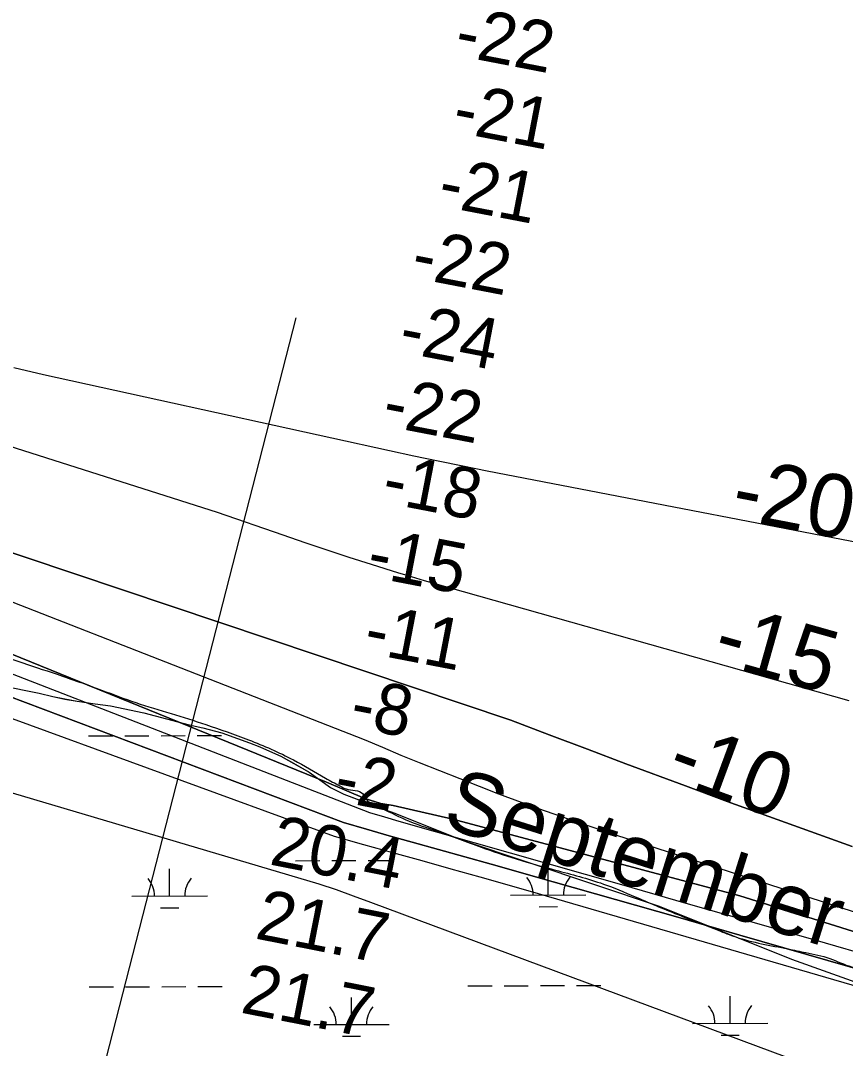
# Model space of a CAD drawing. Extents: x 3361039 to 3398939, y 576572 to 602007.
# Drawn here: x 3394047 to 3395141, y 583372 to 584734 of the extents above; entities that cross this region are included whole.
import ezdxf

# ---------------------------------------------------------------- set-up
doc = ezdxf.new("R2010")
doc.units = 0
for name, color, linetype in [('V-RIVR-EDGE', 7, 'Continuous'), ('V-RIVR-IDEN', 7, 'Continuous'), ('V-RIVR-RANG', 7, 'Continuous'), ('V-SITE-VEGE', 7, 'Continuous'), ('V-TOPO-DPTH', 7, 'Continuous'), ('V-TOPO-MINR', 7, 'Continuous'), ('V-TOPO-MINR-IDEN', 7, 'Continuous'), ('V-TOPO-WATR', 7, 'Continuous'), ('V-WETL-SWMP', 7, 'Continuous')]:
    doc.layers.add(name, color=color, linetype=linetype)

msp = doc.modelspace()

# ---------------------------------------------------------------- linework, layer by layer
at = {"layer": 'V-RIVR-EDGE'}
msp.add_spline([(3387368.6, 585771), (3387389, 585767.6), (3387407.3, 585766.1), (3387418.2, 585761.7), (3387425.5, 585756.5), (3387441.6, 585752.8), (3387452.6, 585751.4), (3387462.1, 585753.9), (3387477.4, 585758.2), (3387482.9, 585759.3), (3387491.7, 585759.3), (3387502.3, 585758.2), (3387510.3, 585756.3), (3387521.6, 585753), (3387530.1, 585752.3), (3387538.5, 585752.2), (3387549.8, 585752.2), (3387558.9, 585755.5), (3387571.4, 585756.9), (3387583.4, 585757.3), (3387598.4, 585756.1), (3387629.8, 585749.5), (3387659.8, 585743.5), (3387703.3, 585736.8), (3387727.4, 585734.2), (3387739.1, 585733.5), (3387750.8, 585734.2), (3387753.7, 585731.6), (3387763.2, 585723.9), (3387774.5, 585720.6), (3387790.6, 585719.8), (3387800.1, 585721.6), (3387814, 585720.1), (3387824.6, 585720.1), (3387847.3, 585714.2), (3387884.2, 585709.4), (3387930.2, 585702.7), (3387980.6, 585701.1), (3388035.1, 585696.5), (3388076, 585694.6), (3388096.9, 585693.8), (3388120.3, 585690.5), (3388145.1, 585685.3), (3388171.8, 585682.3), (3388198.8, 585676.8), (3388222.6, 585669.4), (3388245.6, 585660.6), (3388260.9, 585655.4), (3388279.6, 585655.4), (3388291.3, 585658.3), (3388298.9, 585663.7), (3388299.3, 585666.3), (3388299, 585670.7), (3388290.6, 585674.4), (3388291.7, 585677.3), (3388293.9, 585678.4), (3388303, 585677.6), (3388318.7, 585676.5), (3388334.1, 585672.8), (3388354.1, 585663.6), (3388357.1, 585659.9), (3388363.3, 585658.1), (3388368.4, 585658.1), (3388371, 585661), (3388375.3, 585662.1), (3388379, 585661.3), (3388383, 585659.1), (3388383.7, 585654.4), (3388384.1, 585649.3), (3388389.9, 585647.4), (3388406, 585642.3), (3388468.9, 585637.7), (3388491.5, 585635.8), (3388534.6, 585628.4), (3388578.1, 585619.2), (3388610.6, 585613.6), (3388635.9, 585612.1), (3388727.9, 585599.4), (3388768.5, 585591.7), (3388822.6, 585580.9), (3388865, 585570.6), (3388906.6, 585562.8), (3388924.1, 585559.5), (3388938.8, 585562), (3388961.4, 585563.4), (3388974.2, 585560.1), (3389007.5, 585553.4), (3389018.8, 585554.5), (3389027.2, 585555.9), (3389037.1, 585555.9), (3389051.7, 585553.7), (3389061.2, 585553.3), (3389081.3, 585552.1), (3389098.1, 585551), (3389120.4, 585548.7), (3389143.4, 585546.5), (3389160.2, 585542.1), (3389200.8, 585534.7), (3389222.3, 585525.1), (3389247.2, 585519.2), (3389280.4, 585509.6), (3389307.5, 585497.8), (3389334.5, 585487.2), (3389349.5, 585483.1), (3389361.5, 585483.1), (3389382.7, 585479), (3389397, 585476.8), (3389416.7, 585468.7), (3389441.9, 585458.4), (3389464.9, 585451.4), (3389479.5, 585449.2), (3389506.2, 585446.2), (3389533.2, 585447.2), (3389558.5, 585444.2), (3389577.8, 585437.9), (3389603.4, 585431.3), (3389618.7, 585425.1), (3389639.2, 585415.1), (3389657.8, 585410.3), (3389693.2, 585404.8), (3389768.9, 585383), (3389806.5, 585373), (3389854.3, 585362.3), (3389881.7, 585358.6), (3389913.9, 585354.5), (3389953.7, 585349.3), (3390008.2, 585341.8), (3390037.8, 585336.3), (3390074.3, 585327.8), (3390128, 585312.7), (3390164.5, 585301.6), (3390200.7, 585289.8), (3390292.7, 585255.6), (3390327.1, 585241.3), (3390360.7, 585231.7), (3390404.5, 585221), (3390454.9, 585214.3), (3390483.1, 585210.5), (3390491.8, 585209.4), (3390494.4, 585207.2), (3390501.3, 585201), (3390507.9, 585200.6), (3390527.3, 585196.2), (3390545.9, 585195), (3390557.6, 585194.3), (3390574.4, 585189.8), (3390605.5, 585179.5), (3390698.6, 585148.2), (3390763.2, 585126.9), (3390811.1, 585111), (3390852.4, 585097.8), (3390900.9, 585081.6), (3390948.1, 585063.5), (3390993.7, 585048.4), (3391036.8, 585031.9), (3391070.8, 585020.1), (3391140.5, 584997.6), (3391201.5, 584974.1), (3391247.5, 584957.5), (3391310.7, 584933.6), (3391362.2, 584914.8), (3391400.6, 584900.1), (3391441.8, 584885.7), (3391505.4, 584861.1), (3391563.5, 584841.9), (3391658.8, 584807.3), (3391712.8, 584786), (3391758.8, 584767.3), (3391796.1, 584749.6), (3391880.4, 584718.3), (3391926.8, 584701.4), (3391969.2, 584685.2), (3392003.9, 584666.9), (3392040, 584650.3), (3392077.6, 584636), (3392135.7, 584613.2), (3392164.9, 584598.1), (3392196, 584583.8), (3392224.8, 584578.2), (3392263.5, 584567.9), (3392290.6, 584559.8), (3392322.7, 584546.5), (3392396.5, 584512.7), (3392439.9, 584496.2), (3392471.7, 584484.8), (3392502, 584473.3), (3392510.8, 584467.5), (3392535.2, 584458.3), (3392606.1, 584432.9), (3392632.4, 584421.5), (3392666.7, 584406.8), (3392715.6, 584386.9), (3392777.4, 584364.8), (3392827, 584348.3), (3392863.6, 584335.4), (3392897.9, 584321.8), (3392928.6, 584307.8), (3392965.4, 584294.9), (3393010, 584279.1), (3393054.6, 584263.2), (3393092.5, 584248.5), (3393195.2, 584206.6), (3393234.2, 584187.9), (3393264.5, 584173.5), (3393294.1, 584162.1), (3393336.8, 584147.4), (3393374.5, 584136.3), (3393402.2, 584127.5), (3393414.3, 584119.8), (3393435.4, 584109.1), (3393459.2, 584098.1), (3393478.9, 584087.5), (3393513.6, 584076.4), (3393541.7, 584067.2), (3393588.1, 584047.4), (3393643.2, 584028.9), (3393668.4, 584018.3), (3393699.8, 584005), (3393737.1, 583991.8), (3393781.7, 583976), (3393884.7, 583943.2), (3393927, 583928.8), (3393981.1, 583908.2), (3394043.9, 583885.4), (3394095.8, 583868.1), (3394154.9, 583847.1), (3394200.2, 583830.5), (3394247, 583816.2), (3394293, 583801.4), (3394349.6, 583781.2), (3394409.1, 583754.7), (3394451.8, 583730.5), (3394470.5, 583720.2), (3394481.8, 583715.4), (3394494.2, 583713.6), (3394502.6, 583708.1), (3394507.3, 583700.4), (3394511.3, 583697.8), (3394522.7, 583692.3), (3394557.3, 583675.8), (3394600.4, 583659.9), (3394658.1, 583638.9), (3394704.5, 583623.5), (3394760.4, 583607.6), (3394824, 583588.8), (3394867.8, 583570.8), (3394925.9, 583546.9), (3394972.2, 583528.9), (3394995.6, 583520), (3395064.7, 583504.2), (3395088.4, 583499.3), (3395120.2, 583491.6), (3395149.1, 583480.5), (3395173.2, 583476.8), (3395201.3, 583471.3), (3395236.4, 583459.9), (3395256.8, 583451.8), (3395280.9, 583445.5), (3395300.3, 583445.1), (3395316.7, 583440.7), (3395324.4, 583433.3), (3395335.3, 583426), (3395353.6, 583417.9), (3395398.9, 583403.9), (3395426.3, 583397.2), (3395442, 583391), (3395455.9, 583383.3), (3395476, 583377.8), (3395495.7, 583369.3), (3395511, 583368.2), (3395530.4, 583365.9), (3395550.5, 583361.8), (3395654.6, 583334.9), (3395704.7, 583322.4), (3395743.7, 583306.9), (3395765.3, 583295.5), (3395788.3, 583286.3), (3395816.4, 583278.9), (3395861.7, 583270.8), (3395916.2, 583261.5), (3395960.7, 583252.6), (3396008.6, 583242.6), (3396060.8, 583230.5), (3396093.4, 583222.3), (3396135.4, 583208.7), (3396170.1, 583199.8), (3396204.4, 583191.3), (3396254.8, 583177.3), (3396301.2, 583165.9), (3396364.4, 583152.9), (3396399.1, 583144.4), (3396426.9, 583138.5), (3396463.1, 583133), (3396489.8, 583132.9), (3396523.4, 583130.2), (3396607.8, 583114), (3396670.3, 583102.1), (3396708.3, 583095.4), (3396743, 583089.5), (3396775.1, 583083.9)], degree=3, dxfattribs=at)
at = {"layer": 'V-RIVR-RANG'}
msp.add_line((3394114.5, 583178.3), (3394413, 584340.6), dxfattribs=at)
at = {"layer": 'V-SITE-VEGE'}
for p, q in [((3394037.2, 583850), (3394056.8, 583846.3)), ((3394056.8, 583846.3), (3394072.3, 583842.9)), ((3394072.3, 583842.9), (3394090.2, 583838.7)), ((3394090.2, 583838.7), (3394106, 583835.3)), ((3394106, 583835.3), (3394122.6, 583832.4)), ((3394122.6, 583832.4), (3394146.4, 583829.1)), ((3394146.4, 583829.1), (3394166.6, 583826.2)), ((3394166.6, 583826.2), (3394210.7, 583817)), ((3394210.7, 583817), (3394271.2, 583801.2)), ((3394271.2, 583801.2), (3394289.2, 583797.1)), ((3394289.2, 583797.1), (3394314.4, 583790.6)), ((3394314.4, 583790.6), (3394335.2, 583783.2)), ((3394335.2, 583783.2), (3394350.9, 583777.4)), ((3394350.9, 583777.4), (3394364.6, 583772.1)), ((3394364.6, 583772.1), (3394381.5, 583764.6)), ((3394381.5, 583764.6), (3394392.5, 583759.5)), ((3394392.5, 583759.5), (3394430, 583738.3)), ((3394430, 583738.3), (3394458.5, 583717.9)), ((3394458.5, 583717.9), (3394476.2, 583709.2)), ((3394476.2, 583709.2), (3394524.9, 583690.9)), ((3394524.9, 583690.9), (3394543.8, 583684.1)), ((3394543.8, 583684.1), (3394632.9, 583648.2)), ((3394632.9, 583648.2), (3394894, 583560.7)), ((3394894, 583560.7), (3395069.2, 583490.4)), ((3395069.2, 583490.4), (3395220.2, 583436.8))]:
    msp.add_line(p, q, dxfattribs=at)
at = {"layer": 'V-TOPO-DPTH'}
for points in [[(3395292.5, 583438.3), (3395001.1, 583522.6), (3394918.6, 583546.3), (3394836.2, 583569.8), (3394753.6, 583593.2), (3394671.1, 583616.4), (3394566.6, 583645.6), (3394536.2, 583654.1), (3394505.9, 583662.8), (3394475.7, 583671.6), (3393772.5, 583936.8), (3393756.9, 583941.8), (3393741.3, 583946.8), (3393068.1, 584211), (3393041, 584220.8), (3393013.8, 584230.7), (3392986.7, 584240.6), (3392333.6, 584495.2)], [(3395337.7, 583469.1), (3395000.8, 583574.7), (3394620.5, 583676.1), (3394541.3, 583694.2), (3394525.2, 583696.7), (3394503.9, 583703.6), (3394452.9, 583725), (3393786.9, 583995.7), (3393773.3, 584000.9), (3393615.1, 584076.2), (3393436.5, 584149.8), (3393313.1, 584198.7), (3393092, 584272.4), (3393059.6, 584279.3), (3393026.4, 584287.1), (3392928.6, 584331.6), (3392676, 584440.3)], [(3392676, 584440.3), (3392928.6, 584331.6), (3393026.4, 584287.1), (3393059.6, 584279.3), (3393092, 584272.4), (3393313.1, 584198.7), (3393436.5, 584149.8), (3393615.1, 584076.2), (3393773.3, 584000.9), (3393786.9, 583995.7), (3394452.9, 583725), (3394503.9, 583703.6), (3394525.2, 583696.7), (3394541.3, 583694.2), (3394620.5, 583676.1), (3395000.8, 583574.7), (3395337.7, 583469.1)], [(3394038.4, 584274.4), (3394078, 584265.3), (3394536.6, 584164.5), (3394568.9, 584157.5), (3394601.2, 584150.7), (3394633.6, 584144.2), (3394665.9, 584137.8), (3395270.7, 584021.1)], [(3394038.4, 584274.4), (3394078, 584265.3), (3394536.6, 584164.5), (3394568.9, 584157.5), (3394601.2, 584150.7), (3394633.6, 584144.2), (3394665.9, 584137.8), (3395270.7, 584021.1)], [(3395149.8, 583640.1), (3395094.5, 583659.7), (3395039.2, 583679.6), (3394984, 583699.7), (3394928.9, 583720.1), (3394849.9, 583749.6), (3394799, 583768.7), (3394748.2, 583787.9), (3394697.5, 583807.4), (3393861, 584087.8)], [(3393861, 584087.8), (3394697.5, 583807.4), (3394748.2, 583787.9), (3394799, 583768.7), (3394849.9, 583749.6), (3394928.9, 583720.1), (3394984, 583699.7), (3395039.2, 583679.6), (3395094.5, 583659.7), (3395149.8, 583640.1)]]:
    msp.add_lwpolyline(points, dxfattribs=at)
at = {"layer": 'V-TOPO-MINR'}
for points in [[(3392413.4, 584588.1), (3393024.8, 584355.3), (3393588.5, 584137.2), (3393654.6, 584111.3), (3393783.7, 584062.7), (3394503, 583781.8), (3394527.2, 583771.3), (3394551.6, 583761.1), (3394576, 583751.1), (3394629.6, 583729.8), (3394681.1, 583709.8), (3394732.9, 583690.6), (3394785, 583672.4), (3394837.4, 583655), (3395352.5, 583489)], [(3392333.6, 584495.2), (3392986.7, 584240.6), (3393013.8, 584230.7), (3393041, 584220.8), (3393068.1, 584211), (3393741.3, 583946.8), (3393756.9, 583941.8), (3393772.5, 583936.8), (3394475.7, 583671.6), (3394505.9, 583662.8), (3394536.2, 583654.1), (3394566.6, 583645.6), (3394671.1, 583616.4), (3394753.6, 583593.2), (3394836.2, 583569.8), (3394918.6, 583546.3), (3395001.1, 583522.6), (3395292.5, 583438.3)], [(3392503.1, 584471.7), (3392936.5, 584291.9), (3392995.9, 584270.1), (3393008.4, 584265.6), (3393021, 584261), (3393033.6, 584256.5), (3393046.1, 584251.9), (3393763.4, 583970.9), (3393793.1, 583961.2), (3393822.8, 583951.3), (3394510.2, 583684.8), (3394529.7, 583679.2), (3394549.1, 583673.6), (3394843.9, 583589.4), (3394929.4, 583564.9), (3395014.9, 583540.5), (3395100.4, 583516), (3395185.8, 583491.4)], [(3392293, 584386.4), (3392910, 584097.1), (3392952.5, 584078.2), (3393572.4, 583855.2), (3393597.9, 583846.3), (3393623.5, 583837.4), (3393649.1, 583828.7), (3393674.8, 583820), (3393716.8, 583805.9), (3393721.5, 583804.4), (3393726.1, 583802.9), (3394442.8, 583590.5), (3394465.7, 583582.8), (3394488.5, 583574.7), (3394511.2, 583566.1), (3395350.3, 583253.7)], [(3394038.4, 584274.4), (3394078, 584265.3), (3394536.6, 584164.5), (3394568.9, 584157.5), (3394601.2, 584150.7), (3394633.6, 584144.2), (3394665.9, 584137.8), (3395270.7, 584021.1)], [(3393853.7, 584227.5), (3394308.1, 584083.1), (3394395.2, 584052.8), (3394424.3, 584042.7), (3394453.5, 584032.9), (3394482.8, 584023.3), (3394512.1, 584014), (3394548.3, 584002.7), (3394559.6, 583999.2), (3394571, 583995.8), (3394582.3, 583992.4), (3394593.7, 583989.2), (3395145.5, 583833.3)], [(3393861, 584087.8), (3394697.5, 583807.4), (3394748.2, 583787.9), (3394799, 583768.7), (3394849.9, 583749.6), (3394928.9, 583720.1), (3394984, 583699.7), (3395039.2, 583679.6), (3395094.5, 583659.7), (3395149.8, 583640.1)], [(3393788.1, 583900.1), (3394463.4, 583653.6), (3394502, 583642.6), (3394540.6, 583631.8), (3394579.3, 583621.2), (3394617.9, 583610.5), (3394656.5, 583599.7), (3394695.1, 583588.8), (3394733.6, 583577.7), (3395334.6, 583402.9)]]:
    msp.add_lwpolyline(points, dxfattribs=at)
at = {"layer": 'V-TOPO-WATR'}
msp.add_lwpolyline([(3395337.7, 583469.1), (3395000.8, 583574.7), (3394620.5, 583676.1), (3394541.3, 583694.2), (3394525.2, 583696.7), (3394503.9, 583703.6), (3394452.9, 583725), (3393786.9, 583995.7), (3393773.3, 584000.9), (3393615.1, 584076.2), (3393436.5, 584149.8), (3393313.1, 584198.7), (3393092, 584272.4), (3393059.6, 584279.3), (3393026.4, 584287.1), (3392928.6, 584331.6), (3392676, 584440.3)], dxfattribs=at)
at = {"layer": 'V-WETL-SWMP'}
for p, q in [((3394037.2, 583850), (3394056.8, 583846.3)), ((3394056.8, 583846.3), (3394072.3, 583842.9)), ((3394072.3, 583842.9), (3394090.2, 583838.8)), ((3394090.2, 583838.8), (3394106, 583835.4)), ((3394106, 583835.4), (3394122.6, 583832.5)), ((3394122.6, 583832.5), (3394146.4, 583829.1)), ((3394146.4, 583829.1), (3394166.6, 583826.2)), ((3394166.6, 583826.2), (3394210.7, 583817.1)), ((3394210.7, 583817.1), (3394271.2, 583801.2)), ((3394271.2, 583801.2), (3394289.2, 583797.1)), ((3394289.2, 583797.1), (3394314.4, 583790.6)), ((3394137.7, 583786.5), (3394169.7, 583786.6)), ((3394185.7, 583786.6), (3394217.7, 583786.7)), ((3394233.7, 583786.7), (3394265.7, 583786.8)), ((3394281.7, 583786.9), (3394313.7, 583787)), ((3394314.4, 583790.6), (3394335.2, 583783.2)), ((3394335.2, 583783.2), (3394350.9, 583777.4)), ((3394350.9, 583777.4), (3394364.6, 583772.1)), ((3394364.6, 583772.1), (3394381.5, 583764.6)), ((3394381.5, 583764.6), (3394392.5, 583759.6)), ((3394392.5, 583759.6), (3394409.2, 583750.2)), ((3394409.2, 583750.2), (3394430, 583738.3)), ((3394430, 583738.3), (3394458.5, 583717.9)), ((3394458.5, 583717.9), (3394476.2, 583709.2)), ((3394476.2, 583709.2), (3394504.1, 583698.7)), ((3394504.1, 583698.7), (3394524.9, 583690.9)), ((3394524.9, 583690.9), (3394543.8, 583684.1)), ((3394543.8, 583684.1), (3394632.9, 583648.2)), ((3394632.9, 583648.2), (3394894, 583560.7)), ((3394412.1, 583621.1), (3394444.1, 583621.2)), ((3394460.1, 583621.2), (3394492.1, 583621.3)), ((3394508.1, 583621.3), (3394540.1, 583621.4)), ((3394245.1, 583574.2), (3394245, 583610.2)), ((3394747, 583575.6), (3394747, 583610)), ((3394195.1, 583574), (3394295.1, 583574.3)), ((3394697, 583575.4), (3394797, 583575.7)), ((3394233.2, 583558.7), (3394257.2, 583558.8)), ((3394735.1, 583560.1), (3394759.1, 583560.2)), ((3394894, 583560.7), (3395069.2, 583490.5)), ((3395069.2, 583490.5), (3395209.1, 583440.8)), ((3394138.6, 583453.8), (3394170.6, 583453.9)), ((3394186.6, 583454), (3394218.6, 583454)), ((3394234.6, 583454.1), (3394266.6, 583454.2)), ((3394282.6, 583454.2), (3394314.6, 583454.3)), ((3394640.5, 583455.2), (3394672.5, 583455.3)), ((3394688.5, 583455.3), (3394720.5, 583455.4)), ((3394736.5, 583455.5), (3394768.5, 583455.6)), ((3394784.5, 583455.6), (3394816.5, 583455.7)), ((3394486.1, 583404), (3394486, 583440)), ((3394988, 583405.4), (3394987.9, 583441.4)), ((3394436.1, 583403.9), (3394536.1, 583404.2)), ((3394938, 583405.3), (3395038, 583405.6)), ((3394474.1, 583388.6), (3394498.1, 583388.6)), ((3394976, 583390), (3395000, 583390))]:
    msp.add_line(p, q, dxfattribs=at)
for centre, start, end in [((3394189.9, 583574.5), 359.3865, 40.9302), ((3394300.4, 583574.8), 139.3865, 180.9301), ((3394691.8, 583575.9), 359.3865, 40.9302), ((3394802.3, 583576.2), 139.3865, 180.9301), ((3395043.2, 583406.1), 139.3865, 180.9301), ((3394430.8, 583404.4), 359.3865, 40.9302), ((3394541.3, 583404.7), 139.3865, 180.9301), ((3394932.8, 583405.7), 359.3865, 40.9302)]:
    msp.add_arc(centre, 35.2, start, end, dxfattribs=at)

# ---------------------------------------------------------------- texts
at = {"layer": 'V-RIVR-IDEN'}
msp.add_text('September', height=83, rotation=342.557, dxfattribs=at).set_placement((3394604.4, 583666.6))
at = {"layer": 'V-RIVR-RANG'}
for s, rotation, p in [('-22', 349.0919, (3394620.6, 584688.9)), ('-21', 349.0919, (3394617.8, 584587.6)), ('-21', 349.0919, (3394598.6, 584489.5)), ('-22', 349.0919, (3394563.1, 584394.4)), ('-24', 349.0919, (3394546.8, 584295.8)), ('-22', 349.0919, (3394524.8, 584198.2)), ('-18', 349.0919, (3394524.3, 584096.4)), ('-15', 349.0919, (3394504.1, 583998.5)), ('-11', 349.0919, (3394500.2, 583897.4)), ('-8', 349.0919, (3394481.8, 583799.1)), ('-2', 349.0919, (3394460.6, 583701.3)), ('20.4', 348.8083, (3394375.8, 583616.4)), ('21.7', 348.8083, (3394356.7, 583518.3)), ('21.7', 348.8083, (3394337.5, 583420.1))]:
    msp.add_text(s, height=67, rotation=rotation, dxfattribs=at).set_placement(p)
at = {"layer": 'V-TOPO-MINR-IDEN'}
for s, rotation, p in [('-20', 349.0769, (3394987, 584075.9)), ('-15', 344.2295, (3394962.2, 583885.1)), ('-10', 339.7104, (3394900.5, 583730.6))]:
    msp.add_text(s, height=83, rotation=rotation, dxfattribs=at).set_placement(p)

doc.saveas('drawing.dxf')
